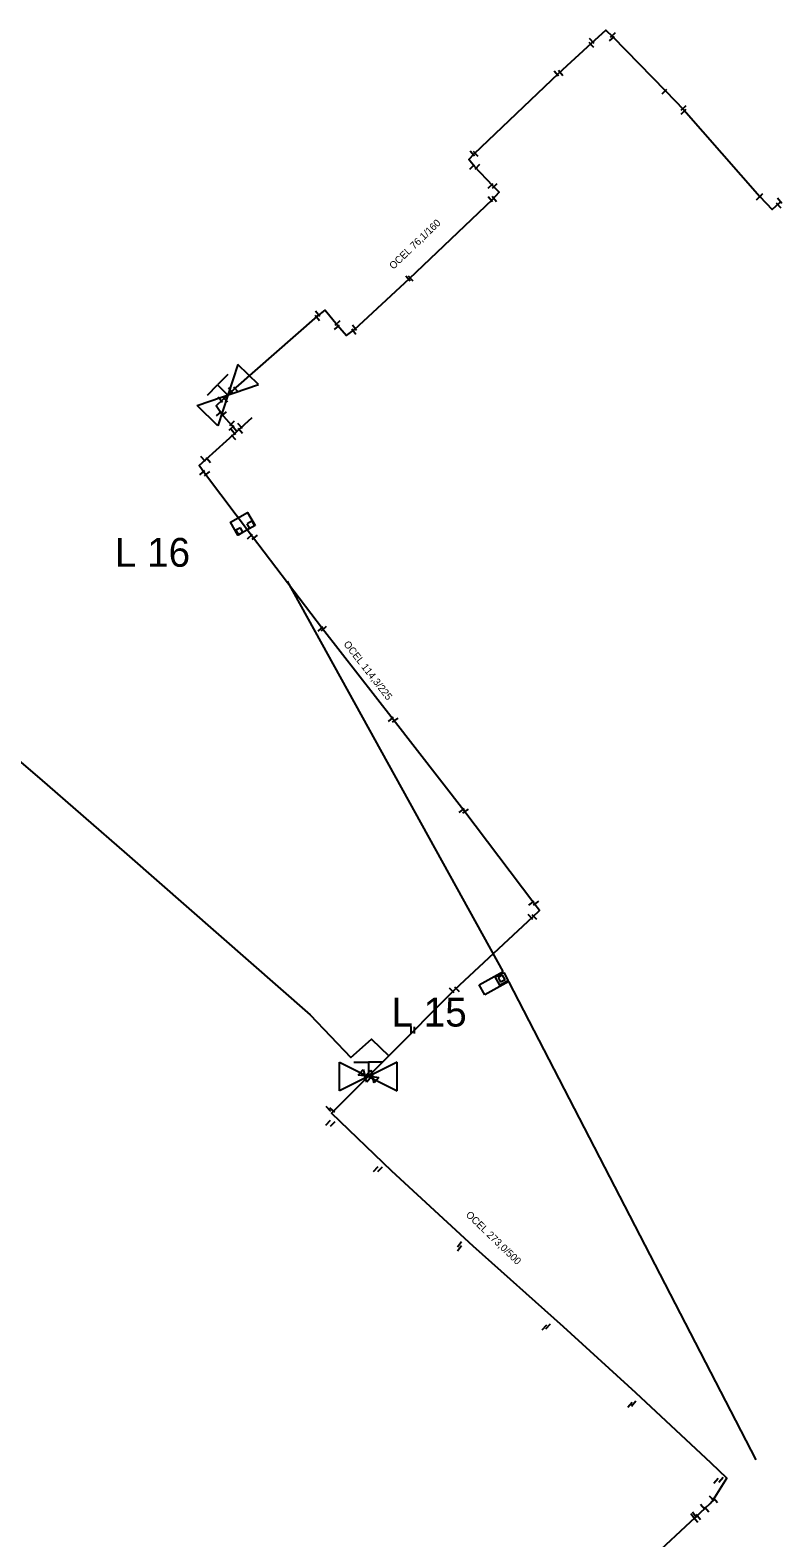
# Model space of a CAD drawing. Extents: x -642943 to -623314, y -1138561 to -1113539.
# Drawn here: x -641707.4 to -641629.3, y -1114043 to -1113886.1 of the extents above; entities that cross this region are included whole.
import ezdxf

# ---------------------------------------------------------------- set-up
doc = ezdxf.new("R2010")
doc.units = 0
for name, color, linetype in [('horkovod armatury', 7, 'Continuous'), ('horkovod dimenze', 7, 'Continuous'), ('horkovod předisol', 7, 'Continuous'), ('horkovod sváry', 7, 'Continuous'), ('horkovod trasa', 7, 'Continuous'), ('horkovod zrušený', 7, 'Continuous'), ('horkovod číslo šachty', 7, 'Continuous'), ('horkovod šachty', 7, 'Continuous')]:
    doc.layers.add(name, color=color, linetype=linetype)

# ---------------------------------------------------------------- blocks, each defined once
blk = doc.blocks.new('POINT_DISPLAY')
blk.add_line((0, 0), (0, 0))
blk = doc.blocks.new('SPH_2')
at = {"layer": 'horkovod sváry'}
blk.add_line((0, -0.035), (0, 0.035), dxfattribs=at)
blk = doc.blocks.new('SPH_1')
at = {"layer": 'horkovod sváry'}
blk.add_line((0, -0.035), (0, 0.035), dxfattribs=at)
blk = doc.blocks.new('SPH')
at = {"layer": 'horkovod sváry'}
blk.add_line((0, -0.035), (0, 0.035), dxfattribs=at)
blk = doc.blocks.new('SCH_01_95')
at = {"layer": 'horkovod armatury'}
for p, q in [((10, 5), (-10, -5)), ((-10, -5), (-10, 5)), ((-10, 5), (10, -5)), ((-5, 5), (0, 5)), ((0, 5), (0, 0)), ((5, 5), (0, 5)), ((10, -5), (10, 5))]:
    blk.add_line(p, q, dxfattribs=at)
blk = doc.blocks.new('SH')
at = {"layer": 'horkovod armatury'}
for p, q in [((-0.057, -0.039), (-0.056, 0.038)), ((-0.056, 0.038), (0, 0)), ((0.001, 0), (0.058, 0.037)), ((0.058, 0.037), (0.058, -0.039)), ((0.001, 0), (-0.057, -0.039)), ((0.058, -0.039), (0.001, 0))]:
    blk.add_line(p, q, dxfattribs=at)
blk = doc.blocks.new('SCH_01_62')
at = {"layer": 'horkovod armatury'}
for p, q in [((10, 5), (-10, -5)), ((-10, -5), (-10, 5)), ((-10, 5), (10, -5)), ((-5, 5), (0, 5)), ((0, 5), (0, 0)), ((5, 5), (0, 5)), ((10, -5), (10, 5))]:
    blk.add_line(p, q, dxfattribs=at)

msp = doc.modelspace()

# ---------------------------------------------------------------- linework, layer by layer
at = {"layer": 'horkovod předisol'}
for p, q in [((-641685.91, -1113927.88), (-641684.31, -1113926.41)), ((-641650.66, -1114052.42), (-641636.7, -1114039.43))]:
    msp.add_line(p, q, dxfattribs=at)
for points in [[(-641685.91, -1113927.88), (-641686.46, -1113927.21), (-641687.53, -1113926.01), (-641688.07, -1113925.21), (-641687.37, -1113924.55), (-641686.26, -1113923.52), (-641677.52, -1113915.85), (-641676.75, -1113915.24), (-641675.46, -1113916.8), (-641674.52, -1113917.87), (-641673.7, -1113917.26), (-641667.96, -1113911.95), (-641659.35, -1113903.71), (-641658.65, -1113902.96), (-641659.31, -1113902.3), (-641661.2, -1113900.3), (-641661.79, -1113899.55), (-641661.24, -1113898.96), (-641652.45, -1113890.57), (-641649.04, -1113887.47), (-641647.55, -1113886.1), (-641646.86, -1113886.76), (-641641.34, -1113892.42), (-641639.44, -1113894.4), (-641631.55, -1113903.42), (-641630.24, -1113904.75), (-641629.39, -1113903.98)], [(-641670.12, -1113992.84), (-641663.24, -1113985.93), (-641655.15, -1113978.38), (-641654.44, -1113977.7), (-641655.04, -1113976.94), (-641662.33, -1113967.32), (-641669.66, -1113957.85), (-641677.03, -1113948.39), (-641684.3, -1113938.82), (-641689.27, -1113932.19), (-641689.83, -1113931.41), (-641689.16, -1113930.79), (-641685.91, -1113927.88)], [(-641724.65, -1113948.41), (-641706.44, -1113963.94), (-641697.35, -1113971.86), (-641678.29, -1113988.56), (-641674.06, -1113993.01), (-641671.91, -1113991.09), (-641670.12, -1113992.84)], [(-641636.7, -1114039.43), (-641636.35, -1114039.01), (-641634.98, -1114036.78), (-641636.59, -1114035.21), (-641644.44, -1114027.92), (-641651.97, -1114021.03), (-641661.35, -1114012.63), (-641669.79, -1114004.85), (-641676.09, -1113998.79), (-641670.12, -1113992.84)]]:
    msp.add_lwpolyline(points, dxfattribs=at)
at = {"layer": 'horkovod trasa'}
for p, q in [((-641685.91, -1113927.88), (-641684.31, -1113926.41)), ((-641650.66, -1114052.42), (-641636.7, -1114039.43))]:
    msp.add_line(p, q, dxfattribs=at)
for points in [[(-641685.91, -1113927.88), (-641686.46, -1113927.21), (-641687.53, -1113926.01), (-641688.07, -1113925.21), (-641687.37, -1113924.55), (-641686.26, -1113923.52), (-641677.52, -1113915.85), (-641676.75, -1113915.24), (-641675.46, -1113916.8), (-641674.52, -1113917.87), (-641673.7, -1113917.26), (-641667.96, -1113911.95), (-641659.35, -1113903.71), (-641658.65, -1113902.96), (-641659.31, -1113902.3), (-641661.2, -1113900.3), (-641661.79, -1113899.55), (-641661.24, -1113898.96), (-641652.45, -1113890.57), (-641649.04, -1113887.47), (-641647.55, -1113886.1), (-641646.86, -1113886.76), (-641641.34, -1113892.42), (-641639.44, -1113894.4), (-641631.55, -1113903.42), (-641630.24, -1113904.75), (-641629.39, -1113903.98)], [(-641670.12, -1113992.84), (-641663.24, -1113985.93), (-641655.15, -1113978.38), (-641654.44, -1113977.7), (-641655.04, -1113976.94), (-641662.33, -1113967.32), (-641669.66, -1113957.85), (-641677.03, -1113948.39), (-641684.3, -1113938.82), (-641689.27, -1113932.19), (-641689.83, -1113931.41), (-641689.16, -1113930.79), (-641685.91, -1113927.88)], [(-641724.65, -1113948.41), (-641706.44, -1113963.94), (-641697.35, -1113971.86), (-641678.29, -1113988.56), (-641674.06, -1113993.01), (-641671.91, -1113991.09), (-641670.12, -1113992.84)], [(-641636.7, -1114039.43), (-641636.35, -1114039.01), (-641634.98, -1114036.78), (-641636.59, -1114035.21), (-641644.44, -1114027.92), (-641651.97, -1114021.03), (-641661.35, -1114012.63), (-641669.79, -1114004.85), (-641676.09, -1113998.79), (-641670.12, -1113992.84)]]:
    msp.add_lwpolyline(points, dxfattribs=at)
at = {"layer": 'horkovod zrušený'}
for p, q in [((-641658.22, -1113984.06), (-641680.65, -1113943.45)), ((-641660.71, -1113985.44), (-641658.22, -1113984.06)), ((-641658.28, -1113984.44), (-641658.76, -1113984.7)), ((-641658.76, -1113984.7), (-641658.49, -1113985.18)), ((-641658.01, -1113984.92), (-641658.49, -1113985.18)), ((-641658.01, -1113984.92), (-641658.28, -1113984.44)), ((-641660.14, -1113986.49), (-641660.71, -1113985.44)), ((-641657.64, -1113985.11), (-641660.14, -1113986.49)), ((-641631.92, -1114034.87), (-641657.64, -1113985.11))]:
    msp.add_line(p, q, dxfattribs=at)
msp.add_lwpolyline([(-641658.17, -1113984.15), (-641657.69, -1113985.02), (-641658.57, -1113985.5), (-641659.05, -1113984.63), (-641658.17, -1113984.15)], dxfattribs=at)
at = {"layer": 'horkovod šachty'}
for p, q in [((-641685.55, -1113937.88), (-641686.03, -1113938.15)), ((-641685.28, -1113938.35), (-641685.55, -1113937.88)), ((-641684.37, -1113937.21), (-641684.85, -1113937.48)), ((-641684.58, -1113937.96), (-641684.85, -1113937.48)), ((-641684.1, -1113937.68), (-641684.58, -1113937.96)), ((-641684.37, -1113937.21), (-641684.1, -1113937.68)), ((-641686.03, -1113938.15), (-641685.76, -1113938.62)), ((-641685.76, -1113938.62), (-641685.28, -1113938.35))]:
    msp.add_line(p, q, dxfattribs=at)
msp.add_lwpolyline([(-641684.03, -1113937.65), (-641685.81, -1113938.66), (-641686.58, -1113937.31), (-641684.8, -1113936.3), (-641684.03, -1113937.65)], dxfattribs=at)

# ---------------------------------------------------------------- block references
at = {"layer": 'horkovod armatury'}
for name, p, xscale, yscale, rotation in [('SCH_01_95', (-641686.86, -1113924.07), 0.30000592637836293, 0.300005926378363, 45.345870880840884), ('SCH_01_62', (-641672.24, -1113994.99), 0.3000261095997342, 0.30002610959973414, -0.026678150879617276), ('SH', (-641672.61, -1113994.9), 10.0000089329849, 10.0000089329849, -39.9138609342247), ('SH', (-641671.82, -1113994.97), 10.000011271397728, 10.000011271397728, -42.25735704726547)]:
    msp.add_blockref(name, p, dxfattribs=dict(at, xscale=xscale, yscale=yscale, rotation=rotation))
at = {"layer": 'horkovod sváry'}
for name, p, xscale, yscale, rotation in [('SPH_2', (-641649.05, -1113887.65), 9.999998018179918, 9.99999801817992, 44.440615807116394), ('SPH_2', (-641649.01, -1113887.23), 9.999994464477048, 9.99999446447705, 43.12061408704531), ('SPH_2', (-641646.92, -1113886.98), 10.000017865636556, 10.000017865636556, -47.5173333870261), ('SPH_2', (-641646.8, -1113886.57), 9.999968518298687, 9.999968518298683, -46.26978586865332), ('SPH_2', (-641652.71, -1113890.62), 10.000007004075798, 10.000007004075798, 39.95458075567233), ('SPH_2', (-641652.26, -1113890.57), 9.999986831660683, 9.999986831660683, 39.94945690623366), ('SPH_2', (-641641.46, -1113892.48), 9.999992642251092, 9.999992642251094, -43.877215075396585), ('SPH_2', (-641639.46, -1113894.18), 9.999988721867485, 9.999988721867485, -44.605698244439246), ('SPH_2', (-641639.46, -1113894.58), 10.00000248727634, 10.000002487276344, -45.23752283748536), ('SPH_2', (-641661.46, -1113900.32), 10.000015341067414, 10.000015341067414, -45.00000000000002), ('SPH_2', (-641661.44, -1113898.95), 10.000000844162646, 10.000000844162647, 42.00234388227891), ('SPH_2', (-641661.06, -1113898.98), 10.000024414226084, 10.000024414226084, 43.74135481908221), ('SPH_2', (-641660.91, -1113900.3), 10.000023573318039, 10.00002357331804, -43.98930142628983), ('SPH_2', (-641659.53, -1113902.31), 10.000001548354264, 10.000001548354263, -45.430713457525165), ('SPH_2', (-641659.08, -1113902.3), 9.99997529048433, 9.999975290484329, -44.18420706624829), ('SPH_2', (-641631.62, -1113903.5), 10.0000138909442, 10.0000138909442, -45.32732542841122), ('SPH_2', (-641631.48, -1113903.34), 9.999991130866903, 9.999991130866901, -45.07565251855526), ('SPH_2', (-641659.55, -1113903.71), 10.000024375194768, 10.000024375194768, 40.2041620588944), ('SPH_2', (-641659.14, -1113903.69), 10.000006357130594, 10.000006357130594, 40.77397401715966), ('SPH_2', (-641629.56, -1113904.37), 10.000012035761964, 10.000012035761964, 43.15232890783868), ('SPH_2', (-641629.47, -1113903.86), 9.999994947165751, 9.999994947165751, 38.471468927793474), ('SPH_2', (-641668.13, -1113911.97), 10.00000243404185, 10.00000243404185, 40.87271480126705), ('SPH_2', (-641667.83, -1113911.95), 9.999990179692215, 9.999990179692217, 41.340534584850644), ('SPH_2', (-641677.55, -1113916.07), 10.000027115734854, 10.000027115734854, 38.72360164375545), ('SPH_2', (-641677.51, -1113915.63), 10.000027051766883, 10.000027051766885, 37.76458116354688), ('SPH_2', (-641675.49, -1113917.02), 10.000000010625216, 10.000000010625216, -47.53641103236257), ('SPH_2', (-641675.44, -1113916.56), 10.00001501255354, 10.000015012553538, -47.58059751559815), ('SPH_2', (-641673.75, -1113917.48), 10.000004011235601, 10.0000040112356, 37.749160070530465), ('SPH_2', (-641673.68, -1113917.09), 9.999999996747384, 9.99999999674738, 37.65576890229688), ('SPH_2', (-641686.58, -1113923.59), 10.000004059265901, 10.000004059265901, 38.88564874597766), ('SPH_2', (-641685.99, -1113923.51), 10.00001462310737, 10.00001462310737, 42.000836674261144), ('SPH_2', (-641687.63, -1113924.57), 10.000028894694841, 10.000028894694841, 41.58778541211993), ('SPH_2', (-641687.11, -1113924.54), 10.000016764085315, 10.000016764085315, 41.2189803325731), ('SPH_1', (-641687.78, -1113926.02), 9.999982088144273, 9.999982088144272, -50.72345219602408), ('SPH_2', (-641687.26, -1113926.05), 9.999990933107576, 9.999990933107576, -48.036010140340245), ('SPH_2', (-641686.41, -1113927), 10.000012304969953, 10.000012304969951, -46.37073979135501), ('SPH_2', (-641686.45, -1113927.47), 10.000015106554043, 10.000015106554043, -46.41791816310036), ('SPH_2', (-641686.29, -1113927.93), 10.000008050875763, 10.000008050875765, 39.24300173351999), ('SPH_2', (-641686.29, -1113927.93), 10.000008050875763, 10.000008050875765, 39.24300173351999), ('SPH_2', (-641686.25, -1113928.49), 9.999997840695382, 9.999997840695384, 42.97601765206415), ('SPH_2', (-641686.25, -1113928.49), 9.999997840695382, 9.999997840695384, 42.97601765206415), ('SPH_2', (-641685.57, -1113927.29), 10.000013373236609, 10.000013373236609, 41.76504063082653), ('SPH_2', (-641685.55, -1113927.82), 10.000006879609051, 10.000006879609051, 41.34791341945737), ('SPH_2', (-641689.43, -1113930.73), 10.00001193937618, 10.00001193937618, 42.68017868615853), ('SPH_2', (-641688.9, -1113930.86), 9.99998076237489, 9.99998076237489, 39.93487024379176), ('SPH_2', (-641689.5, -1113932.15), 9.999979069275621, 9.999979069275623, -50.31935547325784), ('SPH_2', (-641689.01, -1113932.25), 10.000011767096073, 10.000011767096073, -51.55586503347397), ('SPH_2', (-641684.55, -1113938.78), 10.000002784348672, 10.000002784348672, -47.082692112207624), ('SPH_2', (-641684.05, -1113938.89), 9.99997969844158, 9.99997969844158, -49.24949522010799), ('SPH_2', (-641677.21, -1113948.41), 10.00001444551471, 10.00001444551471, -50.10772877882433), ('SPH_2', (-641676.87, -1113948.37), 10.00002768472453, 10.00002768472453, -48.91961537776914), ('SPH_2', (-641669.9, -1113957.81), 10.000001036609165, 10.000001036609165, -49.703087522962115), ('SPH_2', (-641669.44, -1113957.9), 10.000002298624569, 10.000002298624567, -54.807742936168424), ('SPH_2', (-641662.53, -1113967.31), 10.0000180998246, 10.000018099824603, -54.155485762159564), ('SPH_2', (-641662.12, -1113967.38), 9.999995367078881, 9.999995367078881, -55.93512816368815), ('SPH_2', (-641655.27, -1113976.94), 10.000001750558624, 10.000001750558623, -53.53783669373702), ('SPH_2', (-641654.8, -1113976.96), 9.999979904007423, 9.999979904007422, -52.43137543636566), ('SPH_2', (-641655.39, -1113978.39), 9.999988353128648, 9.99998835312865, 45.06244635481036), ('SPH_2', (-641654.96, -1113978.41), 9.999988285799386, 9.999988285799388, 45.159606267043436), ('SPH_2', (-641663.58, -1113986.03), 10.000004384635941, 10.000004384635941, 44.33156478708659), ('SPH_2', (-641663.02, -1113985.93), 10.000010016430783, 10.000010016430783, 45.24771034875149), ('SPH_2', (-641676.39, -1113998.37), 9.99998826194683, 9.99998826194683, 45.70786900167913), ('SPH_2', (-641675.98, -1113998.47), 9.999971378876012, 9.999971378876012, 48.072857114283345), ('SPH_1', (-641676.43, -1113999.78), 10.0000112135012, 10.000011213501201, -42.3536797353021), ('SPH_2', (-641675.93, -1113999.91), 9.99999070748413, 9.999990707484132, -44.15213281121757), ('SPH_2', (-641671.46, -1114004.61), 9.999999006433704, 9.999999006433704, -44.318168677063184), ('SPH_2', (-641671.02, -1114004.63), 10.000002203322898, 10.0000022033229, -44.029112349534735), ('SPH', (-641662.77, -1114012.86), 9.999993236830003, 9.999993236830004, -38.01456680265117), ('SPH', (-641662.76, -1114012.44), 10.000016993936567, 10.000016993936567, -38.21487474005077), ('SPH_2', (-641653.93, -1114021.08), 9.999990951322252, 9.999990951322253, -41.00415863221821), ('SPH_2', (-641653.55, -1114020.98), 10.000004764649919, 10.000004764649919, -42.43752939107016), ('SPH_1', (-641645.05, -1114029.13), 10.000024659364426, 10.000024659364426, -40.64646837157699), ('SPH_2', (-641644.66, -1114029.02), 9.999999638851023, 9.999999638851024, -40.44189823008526), ('SPH_1', (-641635.57, -1114036.96), 9.999997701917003, 9.999997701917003, -41.86858071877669), ('SPH_2', (-641636.1, -1114037.04), 9.999985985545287, 9.999985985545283, -41.06183604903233), ('SPH_2', (-641637.47, -1114039.79), 9.999994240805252, 9.999994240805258, 39.55899722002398), ('SPH_2', (-641637.08, -1114040.06), 10.00001854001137, 10.000018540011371, 40.953484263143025), ('SPH_2', (-641636.53, -1114038.91), 9.999997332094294, 9.999997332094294, 43.42694833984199), ('SPH_1', (-641636.17, -1114039.1), 9.999990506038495, 9.999990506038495, 42.569335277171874), ('SPH_2', (-641638.5, -1114040.78), 10.000001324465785, 10.000001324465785, 37.981689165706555), ('SPH_2', (-641638.33, -1114040.62), 10.00000125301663, 10.00000125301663, 36.755651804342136), ('SPH_1', (-641638.23, -1114041.12), 9.999992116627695, 9.999992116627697, 40.57739098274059), ('SPH_2', (-641637.94, -1114040.85), 10.00001818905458, 10.00001818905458, 38.98848582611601)]:
    msp.add_blockref(name, p, dxfattribs=dict(at, xscale=xscale, yscale=yscale, rotation=rotation))
at = {"layer": 'horkovod sváry', "xscale": 10, "yscale": 10}
for p in [(-641667.79, -1113990.13), (-641667.43, -1113990.17)]:
    msp.add_blockref('SPH_2', p, dxfattribs=at)
at = {"layer": 'horkovod zrušený'}
msp.add_blockref('POINT_DISPLAY', (-641658.38, -1113984.81), dxfattribs=at)
at = {"layer": 'horkovod šachty'}
for p in [(-641684.47, -1113937.58), (-641685.65, -1113938.25)]:
    msp.add_blockref('POINT_DISPLAY', p, dxfattribs=at)

# ---------------------------------------------------------------- texts
at = {"layer": 'horkovod dimenze'}
for s, rotation, p in [('OCEL 76,1/160', 43.9114, (-641669.64, -1113911.04)), ('OCEL 114,3/225', 307.9415, (-641674.87, -1113950.01)), ('OCEL 273,0/500', 316.0399, (-641662.17, -1114009.45))]:
    msp.add_text(s, height=0.75, rotation=rotation, dxfattribs=at).set_placement(p)
at = {"layer": 'horkovod číslo šachty'}
for s, p in [('L 16', (-641698.59, -1113941.94)), ('L 15', (-641669.83, -1113989.79))]:
    msp.add_text(s, height=3, dxfattribs=at).set_placement(p)

doc.saveas('drawing.dxf')
